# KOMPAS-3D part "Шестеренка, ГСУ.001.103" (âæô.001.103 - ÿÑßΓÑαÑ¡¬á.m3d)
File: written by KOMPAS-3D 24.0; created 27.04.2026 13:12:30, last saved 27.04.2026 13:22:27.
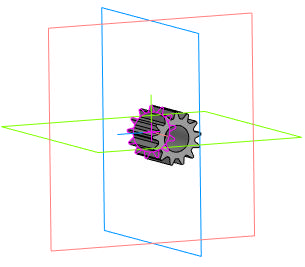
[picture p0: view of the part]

Document properties: Автор: User7; Полное имя файла: C:\Users\User7\Desktop\Двигатель мясорубки\ГСУ.001.103 - Шестеренка.m3d

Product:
- Part/product: Шестеренка  | designation ГСУ.001.103
    Масса: 0.004863

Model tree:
1. Эскиз:1
2. Эскиз:2
3. Элемент выдавливания:1
     Расстояние 1 = 13
4. Эскиз:3  (with: Грань.Элемент выдавливания:1)
5. Элемент выдавливания:2
     Расстояние 2 = 13; Угол 2 = 3

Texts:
  ГСУ.001.103
  Шаг 2
  Шаг 1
